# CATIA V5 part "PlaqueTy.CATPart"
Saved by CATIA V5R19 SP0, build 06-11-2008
Part number: PlaqueTy
Publications: "H", "L", "e", "Li", "P"
Bounding box of the stored display mesh (mm): x 0 to 210, y 0 to 400, z 0 to 200
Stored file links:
  G:\EU_thinkMotion\CFAO_2010\MMS_groupe3\MMS_groupe3\A reprendre\evulliez\evulliez\PlaqueTy.CATPart
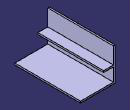
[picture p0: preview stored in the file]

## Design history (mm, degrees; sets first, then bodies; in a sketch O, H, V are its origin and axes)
Parameters
  H = 200 mm
  L = 400 mm
  e = 10 mm
  Li = 80 mm
  P = 200 mm
  b = 60 mm
Body1 (main body)
  Sketch1 on yz-plane, origin (0, 0, 0), H (0, 1, 0), V (0, 0, 1)
    line L1 (0, 0) -> (400, 0)
    line L2 (400, 0) -> (400, 200)
    line L3 (400, 200) -> (0, 200)
    line L4 (0, 200) -> (0, 0)
    length L1 = 400 {= L}
    length L4 = 200 {= H}
    horizontal: L1 H, L3 H
    vertical: L2 V, L4 V
  Pad1: profile Sketch1, direction (1, 0, 0), length 10 {= e}
  Sketch2 on end face of Pad1, origin (10, 0, 0), H (0, 1, 0), V (0, 0, 1)
    line L1 (0, 0) -> (400, 0)
    line L2 (400, 0) -> (400, 10)
    line L3 (400, 10) -> (0, 10)
    line L4 (0, 10) -> (0, 0)
    length L2 = 10 {= e}
    length L1 = 400 {= L}
    horizontal: L1 H, L3 H
    vertical: L2 V, L4 V
  Pad2: profile Sketch2, direction (1, 0, 0), length 200 {= P}
  Sketch3 on end face of Pad1, origin (10, 0, 0), H (0, 1, 0), V (0, 0, 1)
    point P1 (0, 90)
    line L1 (0, 90) -> (400, 90)
    line L2 (400, 90) -> (400, 100)
    line L3 (400, 100) -> (0, 100)
    line L4 (0, 100) -> (0, 90)
    length L2 = 10 {= e}
    length L3 = 400 {= L}
    distance H L1 = 90 {= Li +e}
    coincidence: P1 V
    horizontal: L1 H, L3 H
    vertical: L2 V, L4 V
  Pad3: profile Sketch3, direction (1, 0, 0), length 60 {= b}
